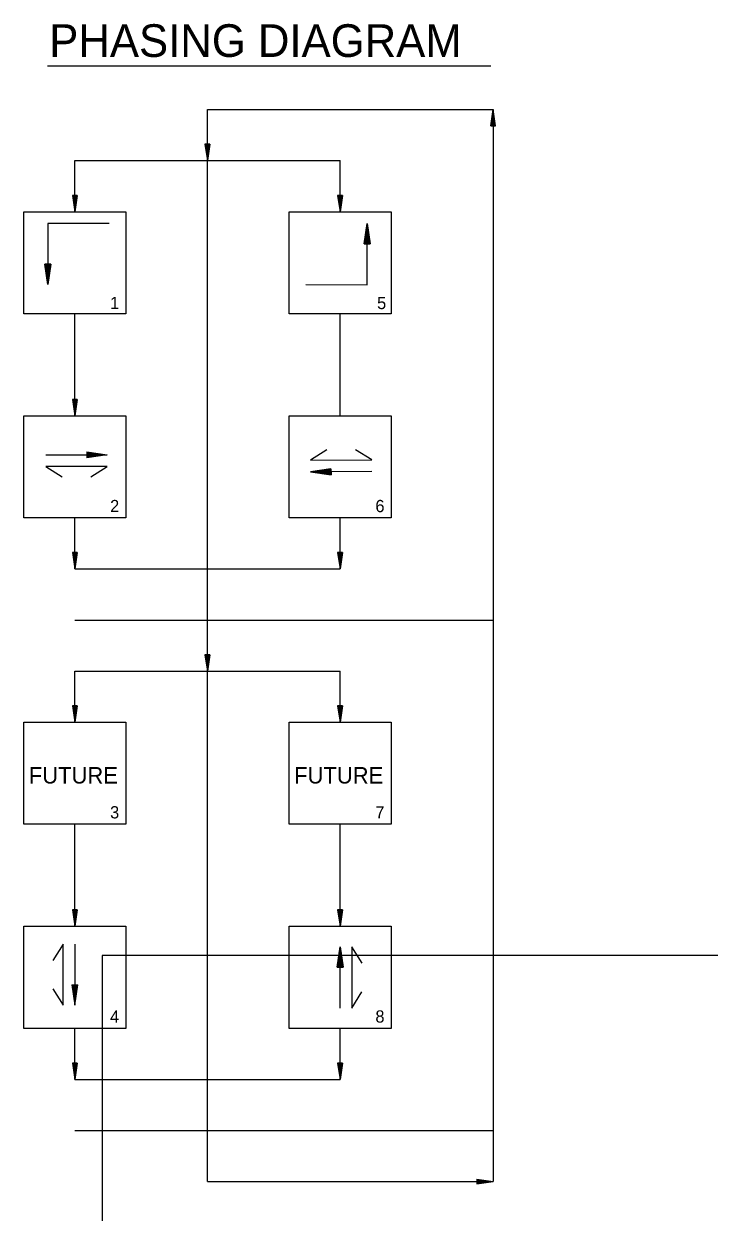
# Model space of a CAD drawing. Extents: x 418532 to 419834, y -565899 to -565283.
# Drawn here: x 418887.1 to 419055.1, y -565573.9 to -565282.9 of the extents above; entities that cross this region are included whole.
import ezdxf

# ---------------------------------------------------------------- set-up
doc = ezdxf.new("R2010")
doc.units = 0
doc.layers.add('Level 57', color=7, linetype='Continuous')
doc.layers.add('Template', color=7, linetype='Continuous')

msp = doc.modelspace()

# ---------------------------------------------------------------- linework, layer by layer
at = {"layer": 'Level 57'}
for p, q in [((418892.95, -565293.16), (419001.61, -565293.16)), ((418932.14, -565566.37), (418932.14, -565303.87)), ((418932.14, -565303.87), (419002.14, -565303.87)), ((419001.54, -565307.87), (419002.14, -565303.87)), ((419001.64, -565307.87), (419002.14, -565304.54)), ((419001.74, -565307.87), (419002.14, -565305.23)), ((419001.84, -565307.87), (419002.14, -565305.89)), ((419001.94, -565307.87), (419002.14, -565306.57)), ((419002.14, -565303.87), (419002.14, -565566.37)), ((419002.74, -565307.87), (419002.14, -565303.87)), ((419002.64, -565307.87), (419002.14, -565304.54)), ((419002.54, -565307.87), (419002.14, -565305.23)), ((419002.44, -565307.87), (419002.14, -565305.89)), ((419002.33, -565307.87), (419002.14, -565306.57)), ((419001.54, -565307.87), (419002.74, -565307.87)), ((419002.04, -565307.87), (419002.14, -565307.24)), ((419002.23, -565307.87), (419002.14, -565307.24)), ((418931.54, -565312.37), (418932.14, -565316.37)), ((418932.74, -565312.37), (418931.54, -565312.37)), ((418931.64, -565312.37), (418932.14, -565315.7)), ((418931.74, -565312.37), (418932.14, -565315.02)), ((418931.84, -565312.37), (418932.14, -565314.35)), ((418931.94, -565312.37), (418932.14, -565313.67)), ((418932.04, -565312.37), (418932.14, -565313)), ((418932.74, -565312.37), (418932.14, -565316.37)), ((418932.33, -565312.37), (418932.14, -565313.67)), ((418932.54, -565312.37), (418932.14, -565315.02)), ((418932.64, -565312.37), (418932.14, -565315.7)), ((418932.44, -565312.37), (418932.14, -565314.35)), ((418932.23, -565312.37), (418932.14, -565313)), ((418899.64, -565328.87), (418899.64, -565316.37)), ((418899.64, -565316.37), (418964.64, -565316.37)), ((418964.64, -565328.87), (418964.64, -565316.37)), ((418899.04, -565324.87), (418899.64, -565328.87)), ((418900.24, -565324.87), (418899.04, -565324.87)), ((418899.14, -565324.87), (418899.64, -565328.2)), ((418899.24, -565324.87), (418899.64, -565327.52)), ((418899.34, -565324.87), (418899.64, -565326.85)), ((418899.44, -565324.87), (418899.64, -565326.17)), ((418899.54, -565324.87), (418899.64, -565325.5)), ((418900.24, -565324.87), (418899.64, -565328.87)), ((418899.83, -565324.87), (418899.64, -565326.17)), ((418900.04, -565324.87), (418899.64, -565327.52)), ((418900.14, -565324.87), (418899.64, -565328.2)), ((418899.94, -565324.87), (418899.64, -565326.85)), ((418899.73, -565324.87), (418899.64, -565325.5)), ((418964.04, -565324.87), (418964.64, -565328.87)), ((418965.24, -565324.87), (418964.04, -565324.87)), ((418964.14, -565324.87), (418964.64, -565328.2)), ((418964.24, -565324.87), (418964.64, -565327.52)), ((418964.34, -565324.87), (418964.64, -565326.85)), ((418964.44, -565324.87), (418964.64, -565326.17)), ((418964.54, -565324.87), (418964.64, -565325.5)), ((418965.24, -565324.87), (418964.64, -565328.87)), ((418964.83, -565324.87), (418964.64, -565326.17)), ((418965.04, -565324.87), (418964.64, -565327.52)), ((418965.14, -565324.87), (418964.64, -565328.2)), ((418964.94, -565324.87), (418964.64, -565326.85)), ((418964.73, -565324.87), (418964.64, -565325.5)), ((418893.04, -565331.73), (418893.02, -565346.73)), ((418908.04, -565331.75), (418893.04, -565331.73)), ((418970.5, -565336.74), (418971.25, -565331.75)), ((418971.25, -565332.58), (418970.62, -565336.74)), ((418971.24, -565346.75), (418971.25, -565331.75)), ((418971.25, -565331.75), (418972, -565336.75)), ((418971.87, -565336.75), (418971.25, -565332.58)), ((418970.75, -565336.74), (418971.25, -565333.44)), ((418971.25, -565334.27), (418970.88, -565336.74)), ((418971.01, -565336.74), (418971.25, -565335.12)), ((418971.25, -565333.44), (418971.75, -565336.75)), ((418971.62, -565336.75), (418971.25, -565334.27)), ((418971.25, -565335.12), (418971.49, -565336.75)), ((418970.5, -565336.74), (418972, -565336.75)), ((418971.25, -565335.96), (418971.13, -565336.75)), ((418971.37, -565336.75), (418971.25, -565335.96)), ((418893.02, -565346.73), (418892.28, -565341.73)), ((418893.78, -565341.73), (418892.28, -565341.73)), ((418892.4, -565341.73), (418893.02, -565345.89)), ((418893.02, -565345.03), (418892.53, -565341.73)), ((418892.66, -565341.73), (418893.03, -565344.2)), ((418893.03, -565343.35), (418892.78, -565341.73)), ((418892.91, -565341.73), (418893.03, -565342.52)), ((418893.53, -565341.73), (418893.02, -565345.03)), ((418893.02, -565345.89), (418893.65, -565341.73)), ((418893.78, -565341.73), (418893.02, -565346.73)), ((418893.03, -565342.52), (418893.15, -565341.73)), ((418893.27, -565341.73), (418893.03, -565343.35)), ((418893.03, -565344.2), (418893.4, -565341.73)), ((418956.24, -565346.73), (418971.24, -565346.75)), ((418899.64, -565378.87), (418899.64, -565353.87)), ((418964.64, -565378.87), (418964.64, -565353.87)), ((418899.04, -565374.87), (418899.64, -565378.87)), ((418900.24, -565374.87), (418899.04, -565374.87)), ((418899.14, -565374.87), (418899.64, -565378.2)), ((418899.24, -565374.87), (418899.64, -565377.52)), ((418899.34, -565374.87), (418899.64, -565376.85)), ((418899.44, -565374.87), (418899.64, -565376.17)), ((418899.54, -565374.87), (418899.64, -565375.5)), ((418900.24, -565374.87), (418899.64, -565378.87)), ((418899.83, -565374.87), (418899.64, -565376.17)), ((418900.04, -565374.87), (418899.64, -565377.52)), ((418900.14, -565374.87), (418899.64, -565378.2)), ((418899.94, -565374.87), (418899.64, -565376.85)), ((418899.73, -565374.87), (418899.64, -565375.5)), ((418902.58, -565387.68), (418907.58, -565388.43)), ((418902.58, -565387.68), (418902.58, -565389.18)), ((418906.74, -565388.43), (418902.58, -565387.81)), ((418902.58, -565387.93), (418905.88, -565388.43)), ((418905.05, -565388.43), (418902.58, -565388.06)), ((418902.58, -565388.19), (418904.2, -565388.43)), ((418892.58, -565388.42), (418907.58, -565388.43)), ((418903.37, -565388.43), (418902.58, -565388.31)), ((418907.58, -565388.43), (418902.58, -565389.18)), ((418902.58, -565389.06), (418906.74, -565388.43)), ((418905.88, -565388.43), (418902.58, -565388.93)), ((418902.58, -565388.8), (418905.05, -565388.43)), ((418904.2, -565388.43), (418902.58, -565388.68)), ((418902.58, -565388.55), (418903.37, -565388.43)), ((418962.41, -565391.81), (418957.41, -565392.58)), ((418972.41, -565392.53), (418957.41, -565392.58)), ((418957.41, -565392.58), (418962.42, -565393.31)), ((418958.25, -565392.57), (418962.41, -565391.94)), ((418962.42, -565393.19), (418958.25, -565392.57)), ((418962.41, -565392.06), (418959.11, -565392.57)), ((418959.11, -565392.57), (418962.42, -565393.06)), ((418959.94, -565392.57), (418962.41, -565392.19)), ((418962.42, -565392.93), (418959.94, -565392.57)), ((418962.41, -565392.32), (418960.79, -565392.57)), ((418960.79, -565392.57), (418962.41, -565392.81)), ((418961.62, -565392.56), (418962.41, -565392.44)), ((418962.41, -565392.68), (418961.62, -565392.56)), ((418962.41, -565391.81), (418962.42, -565393.31)), ((418899.64, -565416.37), (418899.64, -565403.87)), ((418964.64, -565416.37), (418964.64, -565403.87)), ((418964.64, -565416.37), (418964.64, -565403.87)), ((418899.04, -565412.37), (418899.64, -565416.37)), ((418900.24, -565412.37), (418899.04, -565412.37)), ((418899.14, -565412.37), (418899.64, -565415.7)), ((418899.24, -565412.37), (418899.64, -565415.02)), ((418899.34, -565412.37), (418899.64, -565414.35)), ((418899.44, -565412.37), (418899.64, -565413.67)), ((418899.54, -565412.37), (418899.64, -565413)), ((418900.24, -565412.37), (418899.64, -565416.37)), ((418899.83, -565412.37), (418899.64, -565413.67)), ((418900.04, -565412.37), (418899.64, -565415.02)), ((418900.14, -565412.37), (418899.64, -565415.7)), ((418899.94, -565412.37), (418899.64, -565414.35)), ((418899.73, -565412.37), (418899.64, -565413)), ((418964.04, -565412.37), (418964.64, -565416.37)), ((418965.24, -565412.37), (418964.04, -565412.37)), ((418964.04, -565412.37), (418964.64, -565416.37)), ((418965.24, -565412.37), (418964.04, -565412.37)), ((418964.14, -565412.37), (418964.64, -565415.7)), ((418964.14, -565412.37), (418964.64, -565415.7)), ((418964.24, -565412.37), (418964.64, -565415.02)), ((418964.24, -565412.37), (418964.64, -565415.02)), ((418964.34, -565412.37), (418964.64, -565414.35)), ((418964.34, -565412.37), (418964.64, -565414.35)), ((418964.44, -565412.37), (418964.64, -565413.67)), ((418964.44, -565412.37), (418964.64, -565413.67)), ((418964.54, -565412.37), (418964.64, -565413)), ((418964.54, -565412.37), (418964.64, -565413)), ((418965.24, -565412.37), (418964.64, -565416.37)), ((418964.83, -565412.37), (418964.64, -565413.67)), ((418965.04, -565412.37), (418964.64, -565415.02)), ((418965.14, -565412.37), (418964.64, -565415.7)), ((418964.94, -565412.37), (418964.64, -565414.35)), ((418964.73, -565412.37), (418964.64, -565413)), ((418965.24, -565412.37), (418964.64, -565416.37)), ((418964.83, -565412.37), (418964.64, -565413.67)), ((418965.04, -565412.37), (418964.64, -565415.02)), ((418965.14, -565412.37), (418964.64, -565415.7)), ((418964.94, -565412.37), (418964.64, -565414.35)), ((418964.73, -565412.37), (418964.64, -565413)), ((418899.64, -565416.37), (418964.64, -565416.37)), ((418899.64, -565428.87), (419002.14, -565428.87)), ((418931.54, -565437.37), (418932.14, -565441.37)), ((418932.74, -565437.37), (418931.54, -565437.37)), ((418931.64, -565437.37), (418932.14, -565440.7)), ((418931.74, -565437.37), (418932.14, -565440.02)), ((418931.84, -565437.37), (418932.14, -565439.35)), ((418931.94, -565437.37), (418932.14, -565438.67)), ((418932.04, -565437.37), (418932.14, -565438)), ((418932.74, -565437.37), (418932.14, -565441.37)), ((418932.33, -565437.37), (418932.14, -565438.67)), ((418932.54, -565437.37), (418932.14, -565440.02)), ((418932.64, -565437.37), (418932.14, -565440.7)), ((418932.44, -565437.37), (418932.14, -565439.35)), ((418932.23, -565437.37), (418932.14, -565438)), ((418899.64, -565441.37), (418964.64, -565441.37)), ((418899.64, -565453.87), (418899.64, -565441.37)), ((418964.64, -565453.87), (418964.64, -565441.37)), ((418899.04, -565449.87), (418899.64, -565453.87)), ((418900.24, -565449.87), (418899.04, -565449.87)), ((418899.14, -565449.87), (418899.64, -565453.2)), ((418899.24, -565449.87), (418899.64, -565452.52)), ((418899.34, -565449.87), (418899.64, -565451.85)), ((418899.44, -565449.87), (418899.64, -565451.17)), ((418899.54, -565449.87), (418899.64, -565450.5)), ((418900.24, -565449.87), (418899.64, -565453.87)), ((418899.83, -565449.87), (418899.64, -565451.17)), ((418900.04, -565449.87), (418899.64, -565452.52)), ((418900.14, -565449.87), (418899.64, -565453.2)), ((418899.94, -565449.87), (418899.64, -565451.85)), ((418899.73, -565449.87), (418899.64, -565450.5)), ((418964.04, -565449.87), (418964.64, -565453.87)), ((418965.24, -565449.87), (418964.04, -565449.87)), ((418964.14, -565449.87), (418964.64, -565453.2)), ((418964.24, -565449.87), (418964.64, -565452.52)), ((418964.34, -565449.87), (418964.64, -565451.85)), ((418964.44, -565449.87), (418964.64, -565451.17)), ((418964.54, -565449.87), (418964.64, -565450.5)), ((418965.24, -565449.87), (418964.64, -565453.87)), ((418964.83, -565449.87), (418964.64, -565451.17)), ((418965.04, -565449.87), (418964.64, -565452.52)), ((418965.14, -565449.87), (418964.64, -565453.2)), ((418964.94, -565449.87), (418964.64, -565451.85)), ((418964.73, -565449.87), (418964.64, -565450.5)), ((418899.64, -565503.87), (418899.64, -565478.87)), ((418964.64, -565503.87), (418964.64, -565478.87)), ((418899.04, -565499.87), (418899.64, -565503.87)), ((418900.24, -565499.87), (418899.04, -565499.87)), ((418899.14, -565499.87), (418899.64, -565503.2)), ((418899.24, -565499.87), (418899.64, -565502.52)), ((418899.34, -565499.87), (418899.64, -565501.85)), ((418899.44, -565499.87), (418899.64, -565501.17)), ((418899.54, -565499.87), (418899.64, -565500.5)), ((418900.24, -565499.87), (418899.64, -565503.87)), ((418899.83, -565499.87), (418899.64, -565501.17)), ((418900.04, -565499.87), (418899.64, -565502.52)), ((418900.14, -565499.87), (418899.64, -565503.2)), ((418899.94, -565499.87), (418899.64, -565501.85)), ((418899.73, -565499.87), (418899.64, -565500.5)), ((418964.04, -565499.87), (418964.64, -565503.87)), ((418965.24, -565499.87), (418964.04, -565499.87)), ((418964.14, -565499.87), (418964.64, -565503.2)), ((418964.24, -565499.87), (418964.64, -565502.52)), ((418964.34, -565499.87), (418964.64, -565501.85)), ((418964.44, -565499.87), (418964.64, -565501.17)), ((418964.54, -565499.87), (418964.64, -565500.5)), ((418965.24, -565499.87), (418964.64, -565503.87)), ((418964.83, -565499.87), (418964.64, -565501.17)), ((418965.04, -565499.87), (418964.64, -565502.52)), ((418965.14, -565499.87), (418964.64, -565503.2)), ((418964.94, -565499.87), (418964.64, -565501.85)), ((418964.73, -565499.87), (418964.64, -565500.5)), ((418899.64, -565508.21), (418899.64, -565523.21)), ((418963.89, -565513.9), (418964.64, -565508.9)), ((418964.64, -565509.74), (418964.02, -565513.9)), ((418964.66, -565523.9), (418964.64, -565508.9)), ((418964.64, -565508.9), (418965.39, -565513.9)), ((418965.27, -565513.9), (418964.64, -565509.74)), ((418964.15, -565513.9), (418964.64, -565510.6)), ((418964.64, -565511.43), (418964.27, -565513.9)), ((418964.4, -565513.9), (418964.64, -565512.28)), ((418964.64, -565513.11), (418964.53, -565513.9)), ((418964.64, -565510.6), (418965.14, -565513.9)), ((418965.02, -565513.9), (418964.64, -565511.43)), ((418964.64, -565512.28), (418964.89, -565513.9)), ((418964.76, -565513.9), (418964.64, -565513.11)), ((418963.89, -565513.9), (418965.39, -565513.9)), ((418898.89, -565518.21), (418899.64, -565523.21)), ((418898.89, -565518.21), (418900.39, -565518.21)), ((418899.64, -565522.38), (418899.02, -565518.21)), ((418899.14, -565518.21), (418899.64, -565521.52)), ((418899.64, -565520.68), (418899.27, -565518.21)), ((418899.4, -565518.21), (418899.64, -565519.84)), ((418899.64, -565519), (418899.52, -565518.21)), ((418899.64, -565523.21), (418900.39, -565518.21)), ((418900.27, -565518.21), (418899.64, -565522.38)), ((418899.64, -565521.52), (418900.14, -565518.21)), ((418900.01, -565518.21), (418899.64, -565520.68)), ((418899.64, -565519.84), (418899.89, -565518.21)), ((418899.76, -565518.21), (418899.64, -565519)), ((418899.64, -565541.37), (418899.64, -565528.87)), ((418964.64, -565541.37), (418964.64, -565528.87)), ((418899.04, -565537.37), (418899.64, -565541.37)), ((418900.24, -565537.37), (418899.04, -565537.37)), ((418899.14, -565537.37), (418899.64, -565540.7)), ((418899.24, -565537.37), (418899.64, -565540.02)), ((418899.34, -565537.37), (418899.64, -565539.35)), ((418899.44, -565537.37), (418899.64, -565538.67)), ((418899.54, -565537.37), (418899.64, -565538)), ((418900.24, -565537.37), (418899.64, -565541.37)), ((418899.83, -565537.37), (418899.64, -565538.67)), ((418900.04, -565537.37), (418899.64, -565540.02)), ((418900.14, -565537.37), (418899.64, -565540.7)), ((418899.94, -565537.37), (418899.64, -565539.35)), ((418899.73, -565537.37), (418899.64, -565538)), ((418964.04, -565537.37), (418964.64, -565541.37)), ((418965.24, -565537.37), (418964.04, -565537.37)), ((418964.14, -565537.37), (418964.64, -565540.7)), ((418964.24, -565537.37), (418964.64, -565540.02)), ((418964.34, -565537.37), (418964.64, -565539.35)), ((418964.44, -565537.37), (418964.64, -565538.67)), ((418964.54, -565537.37), (418964.64, -565538)), ((418965.24, -565537.37), (418964.64, -565541.37)), ((418964.83, -565537.37), (418964.64, -565538.67)), ((418965.04, -565537.37), (418964.64, -565540.02)), ((418965.14, -565537.37), (418964.64, -565540.7)), ((418964.94, -565537.37), (418964.64, -565539.35)), ((418964.73, -565537.37), (418964.64, -565538)), ((418899.64, -565541.37), (418964.64, -565541.37)), ((418899.64, -565553.87), (419002.14, -565553.87)), ((418932.14, -565566.37), (419002.14, -565566.37)), ((418998.14, -565565.77), (419002.14, -565566.37)), ((418998.14, -565565.77), (418998.14, -565566.97)), ((418998.14, -565565.87), (419001.47, -565566.37)), ((418998.14, -565565.97), (419000.78, -565566.37)), ((418998.14, -565566.07), (419000.12, -565566.37)), ((418998.14, -565566.18), (418999.44, -565566.37)), ((418998.14, -565566.28), (418998.77, -565566.37)), ((418998.14, -565566.97), (419002.14, -565566.37)), ((418998.14, -565566.57), (418999.44, -565566.37)), ((418998.14, -565566.77), (419000.78, -565566.37)), ((418998.14, -565566.87), (419001.47, -565566.37)), ((418998.14, -565566.67), (419000.12, -565566.37)), ((418998.14, -565566.47), (418998.77, -565566.37))]:
    msp.add_line(p, q, dxfattribs=at)
for points in [[(418887.14, -565328.87), (418912.14, -565328.87), (418912.14, -565353.87), (418887.14, -565353.87)], [(418952.14, -565328.87), (418977.14, -565328.87), (418977.14, -565353.87), (418952.14, -565353.87)], [(418887.14, -565378.87), (418912.14, -565378.87), (418912.14, -565403.87), (418887.14, -565403.87)], [(418952.14, -565378.87), (418977.14, -565378.87), (418977.14, -565403.87), (418952.14, -565403.87)], [(418887.14, -565453.87), (418912.14, -565453.87), (418912.14, -565478.87), (418887.14, -565478.87)], [(418952.14, -565453.87), (418977.14, -565453.87), (418977.14, -565478.87), (418952.14, -565478.87)], [(418887.14, -565503.87), (418912.14, -565503.87), (418912.14, -565528.87), (418887.14, -565528.87)], [(418952.14, -565503.87), (418977.14, -565503.87), (418977.14, -565528.87), (418952.14, -565528.87)]]:
    msp.add_lwpolyline(points, close=True, dxfattribs=at)
for points in [[(418961.4, -565387.19), (418957.41, -565389.7), (418972.41, -565389.66), (418968.4, -565387.17)], [(418903.57, -565393.81), (418907.57, -565391.31), (418892.57, -565391.3), (418896.57, -565393.8)], [(418894.26, -565519.21), (418896.76, -565523.21), (418896.76, -565508.21), (418894.26, -565512.21)], [(418970.01, -565512.91), (418967.51, -565508.91), (418967.49, -565523.91), (418970, -565519.91)]]:
    msp.add_lwpolyline(points, dxfattribs=at)
at = {"layer": 'Template'}
msp.add_lwpolyline([(419214.2, -565511.02), (418906.32, -565511.02), (418906.32, -565641.34), (419214.2, -565641.34)], close=True, dxfattribs=at)

# ---------------------------------------------------------------- texts
at = {"layer": 'Level 57'}
for s, height, p in [('PHASING DIAGRAM', 8, (418893.38, -565290.98)), ('1', 3, (418908.29, -565352.73)), ('5', 3, (418973.7, -565352.73)), ('2', 3, (418908.29, -565402.45)), ('6', 3, (418973.29, -565402.45)), ('FUTURE', 4.025, (418888.38, -565468.9)), ('FUTURE', 4.025, (418953.38, -565468.9)), ('3', 3, (418908.29, -565477.45)), ('7', 3, (418973.29, -565477.45)), ('4', 3, (418908.29, -565527.45)), ('8', 3, (418973.29, -565527.45))]:
    msp.add_text(s, height=height, dxfattribs=at).set_placement(p)

doc.saveas('drawing.dxf')
